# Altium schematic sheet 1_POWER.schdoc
size 302 x 215 mm
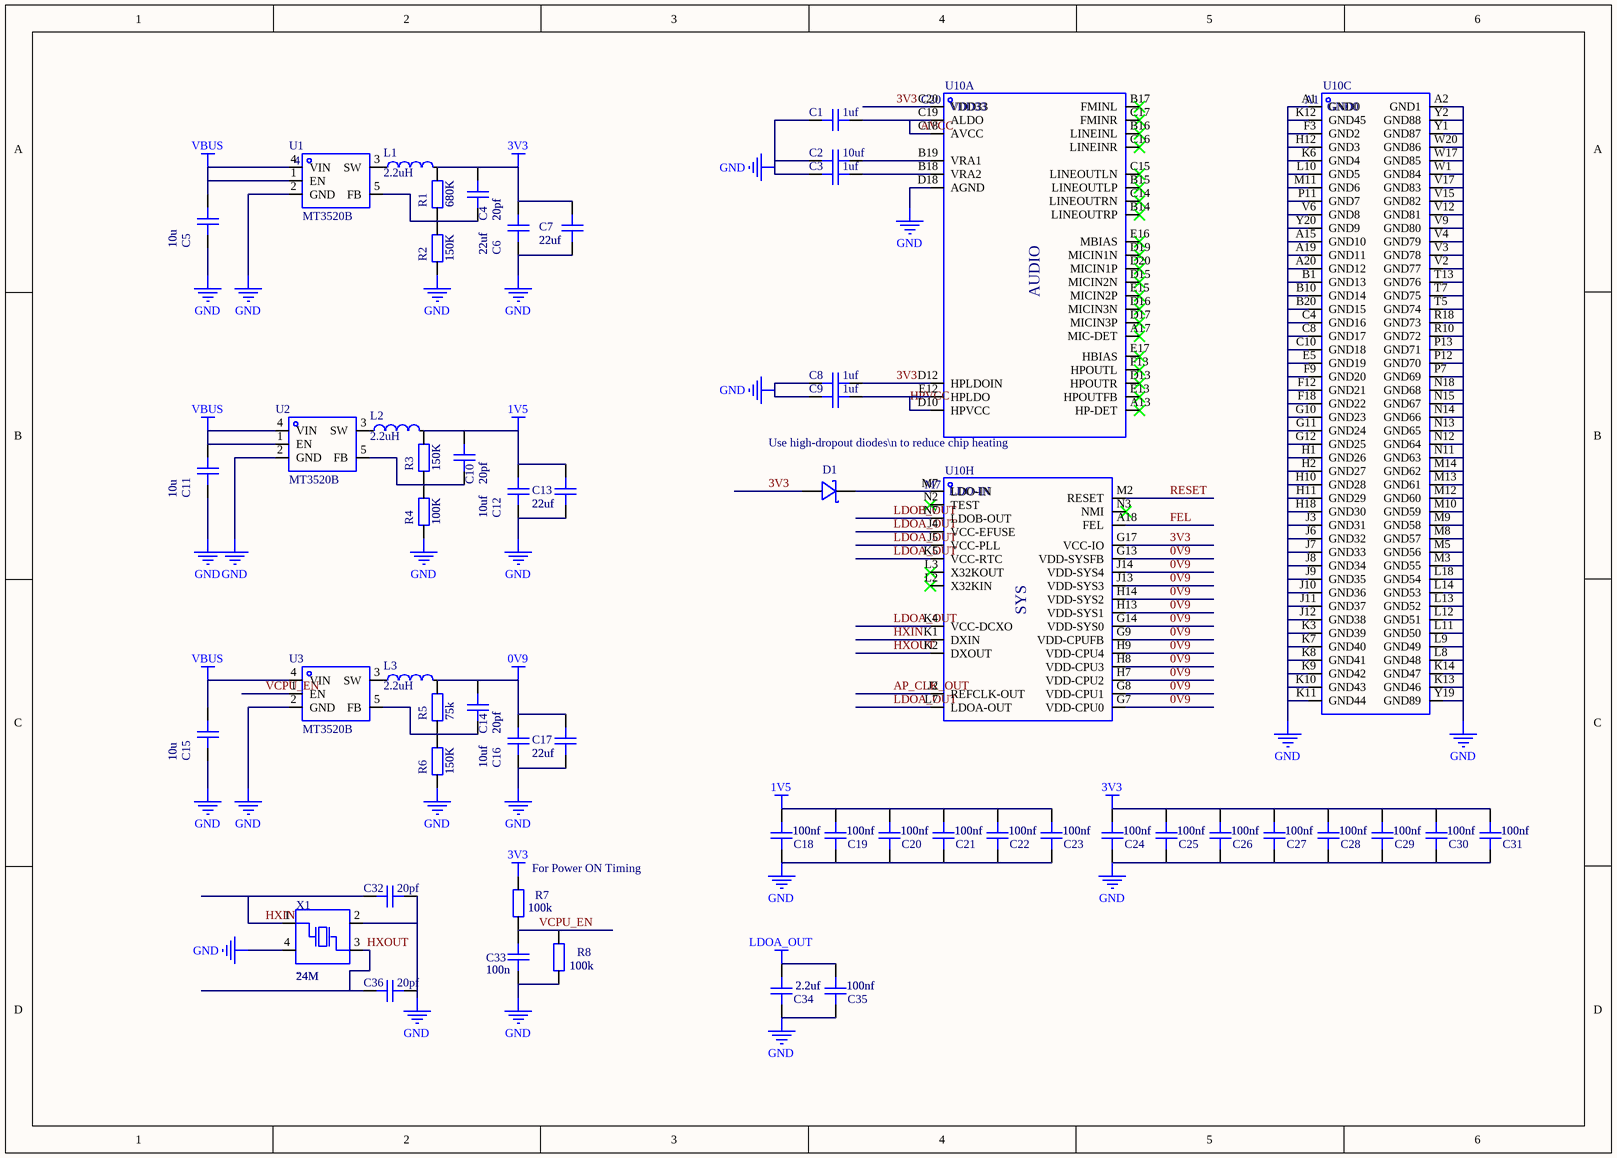
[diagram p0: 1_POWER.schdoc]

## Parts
C1  value 1uf  [C0402]
C2  value 10uf  [C0402]
C3  value 1uf  [C0402]
C4  20pf
C5  10u
C6  22uf
C7  22uf
C8  value 1uf  [C0402]
C9  value 1uf  [C0402]
C10  20pf
C11  10u
C12  10uf
C13  22uf
C14  20pf
C15  10u
C16  10uf
C17  22uf
C18  100nf
C19  100nf
C20  100nf
C21  100nf
C22  100nf
C23  100nf
C24  100nf
C25  100nf
C26  100nf
C27  100nf
C28  100nf
C29  100nf
C30  100nf
C31  100nf
C32  value 20pf
C33  100n
C34  2.2uf
C35  100nf
C36  value 20pf
D1  (no value)  [SOD-323_L1.8-W1.3-LS2.5-RD]
L1  value 2.2uH
L2  value 2.2uH
L3  value 2.2uH
R1  680K
R2  150K
R3  150K
R4  100K
R5  75k
R6  150K
R7  100k
R8  100k
U1  Manufacturer Part: MT3520B  NUMBER: 4
U2  Manufacturer Part: MT3520B
U3  Manufacturer Part: MT3520B
U10  NUMBER: C20  NAME: VDD33  [ALLWINNER D1]  (parts A,C,H of 10)
X1  24M  [OSC-SMD_4P-L3.2-W2.5-BL]

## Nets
0V9: C14.2 C16.2 C17.2 L3.2 R5.2 U10.G7(VDD-CPU0) U10.G8(VDD-CPU1) U10.G9(VDD-CPUFB) U10.G13(VDD-SYSFB) U10.G14(VDD-SYS0) U10.H7(VDD-CPU2) U10.H8(VDD-CPU3) U10.H9(VDD-CPU4) U10.H13(VDD-SYS1) U10.H14(VDD-SYS2) U10.J13(VDD-SYS3) U10.J14(VDD-SYS4)
1V5: C10.2 C12.2 C13.2 C18.2 C19.2 C20.2 C21.2 C22.2 C23.2 L2.2 R3.2
3V3: C4.2 C6.2 C7.2 C8.2 C24.2 C25.2 C26.2 C27.2 C28.2 C29.2 C30.2 C31.2 D1.2(A) L1.2 R1.2 R7.2 U10.C20(VDD33) U10.D12(HPLDOIN) U10.G17(VCC-IO)
GND: C1.1 C2.1 C3.1 C5.1 C6.1 C7.1 C8.1 C9.1 C11.1 C12.1 C13.1 C15.1 C16.1 C17.1 C18.1 C19.1 C20.1 C21.1 C22.1 C23.1 C24.1 C25.1 C26.1 C27.1 C28.1 C29.1 C30.1 C31.1 C32.2 C33.1 C34.1 C35.1 C36.2 R2.1 R4.1 R6.1 R8.1 U1.2(GND) U2.2(GND) U3.2(GND) U10.A1(GND0) U10.A2(GND1) U10.A15(GND10) U10.A19(GND11) U10.A20(GND12) U10.B1(GND13) U10.B10(GND14) U10.B20(GND15) U10.C4(GND16) U10.C8(GND17) U10.C10(GND18) U10.D18(AGND) U10.E5(GND19) U10.F3(GND2) U10.F9(GND20) U10.F12(GND21) U10.F18(GND22) U10.G10(GND23) U10.G11(GND24) U10.G12(GND25) U10.H1(GND26) U10.H2(GND27) U10.H10(GND28) U10.H11(GND29) U10.H12(GND3) U10.H18(GND30) U10.J3(GND31) U10.J6(GND32) U10.J7(GND33) U10.J8(GND34) U10.J9(GND35) U10.J10(GND36) U10.J11(GND37) U10.J12(GND38) U10.K3(GND39) U10.K6(GND4) U10.K7(GND40) U10.K8(GND41) U10.K9(GND42) U10.K10(GND43) U10.K11(GND44) U10.K12(GND45) U10.K13(GND46) U10.K14(GND47) U10.L8(GND48) U10.L9(GND49) U10.L10(GND5) U10.L11(GND50) U10.L12(GND51) U10.L13(GND52) U10.L14(GND53) U10.L18(GND54) U10.M3(GND55) U10.M5(GND56) U10.M8(GND57) U10.M9(GND58) U10.M10(GND59) U10.M11(GND6) U10.M12(GND60) U10.M13(GND61) U10.M14(GND62) U10.N11(GND63) U10.N12(GND64) U10.N13(GND65) U10.N14(GND66) U10.N15(GND67) U10.N18(GND68) U10.P7(GND69) U10.P11(GND7) U10.P12(GND70) U10.P13(GND71) U10.R10(GND72) U10.R18(GND73) U10.T5(GND74) U10.T7(GND75) U10.T13(GND76) U10.V2(GND77) U10.V3(GND78) U10.V4(GND79) U10.V6(GND8) U10.V9(GND80) U10.V12(GND81) U10.V15(GND82) U10.V17(GND83) U10.W1(GND84) U10.W17(GND85) U10.W20(GND86) U10.Y1(GND87) U10.Y2(GND88) U10.Y19(GND89) U10.Y20(GND9) X1.2(GND) X1.4(GND)
LDOA_OUT: C34.2 C35.2 U10.J4(VCC-EFUSE) U10.J5(VCC-PLL) U10.K4(VCC-DCXO) U10.K5(VCC-RTC) U10.L7(LDOA-OUT)
VBUS: C5.2 C11.2 C15.2 U1.1(EN) U1.4(VIN) U2.1(EN) U2.4(VIN) U3.4(VIN)
AP_CLK_OUT: U10.J2(REFCLK-OUT)
AVCC: C1.2 U10.C18(AVCC) U10.C19(ALDO)
FEL: U10.A18(FEL)
HPVCC: C9.2 U10.D10(HPVCC) U10.E12(HPLDO)
HXIN: C32.1 U10.K1(DXIN) X1.1(OSC1)
HXOUT: C36.1 U10.K2(DXOUT) X1.3(OSC2)
LDOB_OUT: U10.N7(LDOB-OUT)
RESET: U10.M2(RESET)
VCPU_EN: C33.2 R7.1 R8.2 U3.1(EN)
NetC2_2: C2.2 U10.B19(VRA1)
NetC3_2: C3.2 U10.B18(VRA2)
NetC4_1: C4.1 R1.1 R2.2 U1.5(FB)
NetC10_1: C10.1 R3.1 R4.2 U2.5(FB)
NetC14_1: C14.1 R5.1 R6.2 U3.5(FB)
NetD1_1: D1.1(C) U10.M7(LDO-IN)
NetL1_1: L1.1 U1.3(SW)
NetL2_1: L2.1 U2.3(SW)
NetL3_1: L3.1 U3.3(SW)

Not connected (* = marked no-connect by the designer): U10 A13(HP-DET)* A17(MIC-DET)* B14(LINEOUTRP)* B15(LINEOUTLP)* B16(LINEINL)* B17(FMINL)* C14(LINEOUTRN)* C15(LINEOUTLN)* C16(LINEINR)* C17(FMINR)* D13(HPOUTR)* D15(MICIN2N)* D16(MICIN3N)* D17(MICIN3P)* D19(MICIN1N)* D20(MICIN1P)* E13(HPOUTFB)* E15(MICIN2P)* E16(MBIAS)* E17(HBIAS)* F13(HPOUTL)* L2(X32KIN)* L3(X32KOUT)* N2(TEST)* N3(NMI)*

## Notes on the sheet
- (near U10) Use high-dropout diodes\n to reduce chip heating
- (near R7) For Power ON Timing

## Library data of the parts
C1-C3 C8 C9 = CAP_0402: Symbol: C1210X7R475K630NT; Convert to PCB: yes; Description: 容值:100nF;精度:±10%;额定电压:16V;温度系数:X7R;
C4 C10 C14 C33 = C0402_3: Symbol: C0402_1; Convert to PCB: yes
C5-C7 C11-C13 C15-C17 = C0603: Symbol: C0402_1; Convert to PCB: yes
C18-C31 C34 C35 = C0402_2: Symbol: C0402; Convert to PCB: yes
C32 C36 = FN15X104K250PNG_1: Manufacturer: PSA(信昌电陶); Add into BOM: yes; Tolerance: ±10%; Voltage Rated: 25V; Temperature Coefficient: X7R; Description: 容值:100nF;精度:±10%;额定电压:25V;温度系数:X7R;; NUMBER: 1; Pin Type: IN
D1 = 1N5819WS: Manufacturer: PJSEMI(平晶微); Symbol: 1N5819WS_C440261; Add into BOM: yes; Reverse Voltage (Vr): 40V; Average Rectified Current (Io): 1A; Forward Voltage (Vf@If): 900mV@3A; Description: 直流反向耐压(Vr):40V;平均整流电流(Io):1A;正向压降(Vf):900mV@3A;
L1-L3 = CKCS201610-2.2uH/M: Manufacturer: CENKER(岑科); Symbol: CKCS201610-2.2UH/M-N; Add into BOM: yes; Tolerance: ±20%; Rated Current: 1.1A; DC Resistance (DCR): 264mΩ; Description: 电感值:2.2uH;精度:±20%;额定电流:1.1A;直流电阻(DCR):264mΩ;
R1-R8 = R0402_2: Symbol: R0402_1; Convert to PCB: yes
U1-U3 = MT3520B_2: Manufacturer: 西安航天民芯; Symbol: MT3520B_1; Pin Type: IN; Add into BOM: yes
U10 = Allwinner D1-H: Pin Type: IN; Add into BOM: yes
X1 = SX32Y024000BC1T_1: Manufacturer: TKD(泰晶); Add into BOM: yes; Description: 晶振类型:-;频率:-;频率公差:-;频率稳定度:-;负载电容:-;工作温度:-;; Pin Type: IN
